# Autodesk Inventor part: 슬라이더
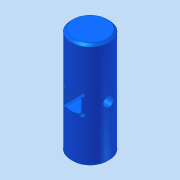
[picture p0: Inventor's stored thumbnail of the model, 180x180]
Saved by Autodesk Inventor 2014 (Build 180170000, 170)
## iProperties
Company: 한국ATC센터
Created: 2015-04
Part Number: 슬라이더
Document SubType Name: Modeling
Designer: KYOUNG IL JANG
Density: 7.85 g/cm^3
Material: 강
Appearance: 청록색
Author: KYOUNG IL JANG
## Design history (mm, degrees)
sketch "스케치1"
  geometry: C1 r 9 at (0, 0); 1 further point
  constraints: 1 centre point, 1 coincident
  dimensions: "d0" = 18 diameter of C1
extrude "돌출1" new body sketch "스케치1" stored distance "d1" = 50; taper "d2" = 0 deg
node "작업 평면1"
sketch "스케치3"
  geometry: L1 (4, 25)-(-4, 25); L2 (-4, 25)-(-4, -25); L3 (-4, -25)-(4, -25); L4 (4, -25)-(4, 25); 3 further points
  constraints: 8 end point, 2 midpoint, 2 parallel, 1 horizontal, 1 horizontal alignment, 1 perpendicular, 1 vertical alignment
  dimensions: "d5" = 8 distance of L1.start L1.end; "d6" = 50 distance of L1.end L2.end
extrude "돌출3" cut sketch "스케치3" stored distance "d7" = 8; taper "d8" = 0 deg
sketch "스케치4"
  geometry: 5 further points
hole "구멍1" sketch "스케치4" at (4, 4), (-4, 4), (-4, -4), (4, -4) diameter "d9" = 2; stored, may be unused: countersink angle "d13" = 90 deg, drill point angle "d15" = 118 deg; dims "d10" = 6, "d11" = 4, "d12" = 2, "d14" = 8
node "작업 평면2"
sketch "스케치5"
  geometry: 1 further point
hole "구멍2" sketch "스케치5" at (0, 0) diameter "d16" = 5; stored, may be unused: countersink angle "d20" = 90 deg, drill point angle "d22" = 118 deg; dims "d17" = 6, "d18" = 4, "d19" = 2, "d21" = 8
chamfer "모따기1" distance "d23" = 1; stored, may be unused: second distance "d24" = 2, angle "d25" = 45 deg
node "솔리드1"
mirror "대칭1"
